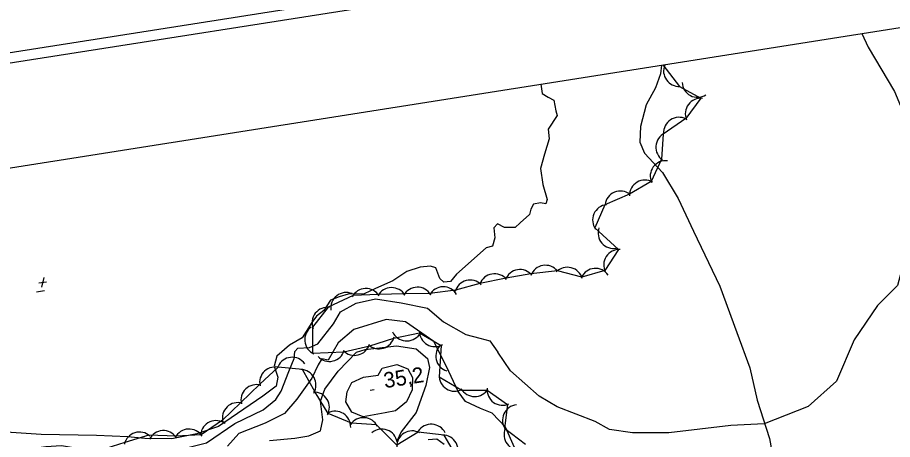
# Model space of a CAD drawing. Extents: x 646142 to 649934, y 5874075 to 5876351.
# Drawn here: x 647215 to 647384.4, y 5875891.3 to 5875973 of the extents above; entities that cross this region are included whole.
import ezdxf

# ---------------------------------------------------------------- set-up
doc = ezdxf.new("R2010")
doc.units = 0
for name, color, linetype in [('Niveau 1', 7, 'Continuous'), ('Niveau 2', 7, 'Continuous'), ('Niveau 22', 7, 'Continuous'), ('Niveau 3', 7, 'Continuous'), ('Niveau 4', 7, 'Continuous'), ('Niveau 44', 7, 'Continuous'), ('Niveau 60', 7, 'Continuous')]:
    doc.layers.add(name, color=color, linetype=linetype)

msp = doc.modelspace()

# ---------------------------------------------------------------- linework, layer by layer
at = {"layer": 'Niveau 1'}
msp.add_lwpolyline([(647311.2, 5875889.81), (647309.49, 5875893.7), (647306.91, 5875896.45), (647304.63, 5875897.32), (647301.71, 5875898.71), (647300.31, 5875900.65), (647298.04, 5875905.47), (647295.59, 5875910.32), (647290.14, 5875914.07), (647286.39, 5875914.56), (647280.1, 5875912.59), (647277.06, 5875910.02), (647275.13, 5875906.7), (647273.95, 5875906.93), (647273.2, 5875905.75), (647272.01, 5875903.19), (647269.11, 5875899.13), (647266.73, 5875896.34), (647262.98, 5875894.51), (647257.86, 5875892.49), (647255.67, 5875890.07)], dxfattribs=at)
at = {"layer": 'Niveau 2'}
for points in [[(647378.44, 5875969.85), (647379.63, 5875967.2), (647384.74, 5875958.65), (647387.38, 5875952.35), (647389.85, 5875944.82), (647390.07, 5875940.83), (647388.75, 5875934.2)], [(647388.75, 5875934.2), (647387.58, 5875929.55), (647385.33, 5875921.14), (647381.43, 5875917.26), (647376.93, 5875910.6), (647373.49, 5875902.65), (647368.06, 5875897.75), (647359.55, 5875894.34), (647353.1, 5875894.04), (647341.09, 5875892.6), (647334.02, 5875892.64), (647329.56, 5875893.29)], [(647266.06, 5875900.7), (647267.53, 5875904.51), (647268.56, 5875907), (647268.72, 5875908.35), (647269.29, 5875908.99), (647271.54, 5875909.1), (647273.15, 5875909.84), (647276.18, 5875913.69), (647277.57, 5875916.04), (647280.59, 5875917.73), (647284.28, 5875918.57), (647289.28, 5875917.74), (647294.36, 5875916.74), (647297.46, 5875914.09), (647301.82, 5875911.62), (647304.49, 5875910.96), (647306.46, 5875910.41), (647308, 5875908.24)], [(647263.83, 5875891.12), (647268.69, 5875891.61), (647271.41, 5875892.06), (647273.69, 5875892.99), (647274.11, 5875895.17), (647273.64, 5875898.77), (647274.51, 5875901.06), (647277.11, 5875904.56), (647280.61, 5875908.21), (647282.29, 5875908.73), (647288.4, 5875909.46), (647292.16, 5875908.85), (647294.36, 5875906.99), (647294.76, 5875905.24), (647294.06, 5875901.81), (647292.21, 5875896.59), (647289.29, 5875892.82), (647288.44, 5875891)], [(647329.56, 5875893.29), (647326.81, 5875894.81), (647319.46, 5875897.67), (647315.96, 5875899.75), (647310.44, 5875904.6), (647308, 5875908.24)], [(647286.17, 5875896.51), (647281.92, 5875895.73), (647279.76, 5875896.61), (647278.58, 5875898.63), (647278.85, 5875900.57), (647279.71, 5875902.39), (647281.98, 5875903.37), (647284.82, 5875903.77), (647285.61, 5875905.12), (647288.47, 5875905.87), (647290.58, 5875904.98), (647291.49, 5875903.34), (647291.38, 5875900.96), (647290.34, 5875898.6), (647288.15, 5875896.88), (647286.17, 5875896.51)], [(647214.46, 5875889.17), (647220.53, 5875889.96), (647223.53, 5875890.15), (647231.77, 5875888.83), (647236.33, 5875888.47), (647245.14, 5875889.07), (647251.64, 5875890.66), (647257.06, 5875894.46), (647262.59, 5875897.1), (647265, 5875899.09), (647266.06, 5875900.7)], [(647294.47, 5875891.32), (647296.18, 5875891.49), (647297.61, 5875890.42)]]:
    msp.add_lwpolyline(points, dxfattribs=at)
at = {"layer": 'Niveau 22'}
msp.add_lwpolyline([(647339.64, 5875963.74), (647339.49, 5875962.05), (647338.47, 5875959.38), (647336.71, 5875956.07), (647335.61, 5875951.88), (647335.45, 5875948.84), (647336.35, 5875946.72), (647339.85, 5875943), (647342.89, 5875937.96), (647345.83, 5875931.63), (647350.93, 5875920.98), (647354.24, 5875912.02), (647356.76, 5875905.19), (647358.18, 5875898.95), (647360.53, 5875891.52), (647361.78, 5875884.69), (647362.72, 5875877.36), (647363.99, 5875873.9), (647367.3, 5875864.85), (647371.22, 5875853.09), (647372.85, 5875844.69), (647375.07, 5875836.12), (647380.22, 5875826)], dxfattribs=at)
at = {"layer": 'Niveau 3'}
for p, q in [((647220.13, 5875922.67), (647219.67, 5875920.82)), ((647220.13, 5875922.67), (647219.67, 5875920.82)), ((647219.14, 5875921.61), (647220.68, 5875921.85)), ((647219.14, 5875921.61), (647220.68, 5875921.85)), ((647218.7, 5875919.92), (647220.28, 5875920.17)), ((647218.7, 5875919.92), (647220.28, 5875920.17)), ((647283.28, 5875900.86), (647284.07, 5875900.98))]:
    msp.add_line(p, q, dxfattribs=at)
at = {"layer": 'Niveau 4'}
msp.add_lwpolyline([(647316.33, 5875960.08), (647316.58, 5875958.24), (647317.7, 5875957.53), (647318.8, 5875956.95), (647319.23, 5875954.89), (647319.44, 5875953.98), (647317.72, 5875951.37), (647317.9, 5875949.52), (647317.04, 5875946.53), (647316.27, 5875943.77), (647316.69, 5875940.67), (647317.56, 5875937.74), (647317.29, 5875936.9), (647316.22, 5875937.14), (647314.86, 5875936.88), (647314.37, 5875935.9), (647314.13, 5875934.83), (647312.32, 5875933.25), (647311.36, 5875932.34), (647309.27, 5875932.37), (647307.93, 5875933.05), (647307.19, 5875932.27), (647307.39, 5875930.32), (647306.96, 5875928.76), (647305.72, 5875928.4), (647299.96, 5875923.29), (647298.82, 5875921.89), (647297.56, 5875921.77), (647296.79, 5875922.5), (647296.01, 5875924.52), (647294.93, 5875924.88), (647292.98, 5875924.68), (647290.4, 5875923.84), (647287.67, 5875922.05), (647284.34, 5875920.55), (647282.12, 5875919.51), (647279, 5875919.43), (647277.31, 5875918.91), (647275.63, 5875918.28), (647274.32, 5875916.29), (647272.92, 5875915.22), (647272, 5875913.96), (647270.09, 5875910.98), (647267.68, 5875909.57), (647265.22, 5875907.46), (647264.71, 5875905.55), (647265.39, 5875903.41), (647265.1, 5875901.63), (647262.5, 5875899.75), (647253.92, 5875893.88), (647249.77, 5875892.42), (647244.88, 5875891.46), (647239.65, 5875891.51), (647236.37, 5875891.88), (647230.31, 5875892.08), (647219.61, 5875892.28), (647212.83, 5875892.76)], dxfattribs=at)
at = {"layer": 'Niveau 44'}
for points in [[(647339.9, 5875963.78), (647343.15, 5875959.63), (647347.29, 5875957.34), (647344.39, 5875953.45), (647339.97, 5875950.42), (647339.62, 5875945.58), (647337.65, 5875941.26), (647333.46, 5875938.8), (647328.7, 5875936.7), (647326.72, 5875932.27), (647331.32, 5875928.06), (647328.67, 5875924), (647324.23, 5875922.74), (647319.53, 5875923.96), (647314.36, 5875923.35), (647309.57, 5875922.55), (647304.52, 5875921.49), (647299.82, 5875920.25), (647294.82, 5875919.6), (647289.97, 5875919.52), (647284.82, 5875919.4), (647279.97, 5875919.2), (647275.12, 5875916.91), (647272.14, 5875913.08), (647272.11, 5875908.05), (647278.16, 5875908.29), (647283.19, 5875909.47), (647287.83, 5875910.91), (647292.83, 5875912), (647297.02, 5875909.55), (647296.63, 5875903.47), (647301.04, 5875900.91), (647305.9, 5875900.87), (647309.85, 5875898.11), (647309.29, 5875893.56), (647313.32, 5875890.46)], [(647300.05, 5875887.98), (647297.61, 5875892.18), (647292.58, 5875892.76), (647288.42, 5875890.26), (647284.52, 5875894.17), (647279.68, 5875894.48), (647275.16, 5875896.37), (647272.64, 5875900.52), (647270.16, 5875904.85), (647265.46, 5875905.31), (647261.91, 5875902.01), (647258.2, 5875898.43), (647254.71, 5875895.05), (647250.56, 5875892.26), (647245.72, 5875891.97), (647240.42, 5875892.2)], [(647240.42, 5875892.2), (647235.79, 5875890.73), (647230.88, 5875889.18), (647226.26, 5875887.71), (647221.14, 5875888.24), (647216.34, 5875888.95), (647211.25, 5875889.73)]]:
    msp.add_lwpolyline(points, dxfattribs=at)
for centre, start, end in [((647343.05, 5875962.63), 158.0824, 273.0218), ((647346.64, 5875960.52), 182.351, 302.3289), ((647347.26, 5875954.34), 83.294, 203.2719), ((647343.05, 5875950.66), 63.4472, 183.4251), ((647341.55, 5875947.87), 115.8757, 235.8536), ((647340.47, 5875942.26), 83.3817, 203.3596), ((647336.45, 5875938.51), 60.4303, 180.4082), ((647331.7, 5875936.4), 52.5962, 172.5742), ((647329.32, 5875933.77), 95.9936, 215.9715), ((647330.38, 5875931.29), 160.9102, 280.8881), ((647331.47, 5875925.07), 86.8811, 206.859), ((647317.19, 5875922.04), 39.5217, 159.4997), ((647321.44, 5875921.65), 15.4721, 135.4501), ((647326.87, 5875921.44), 34.4337, 154.4116), ((647307.33, 5875920.39), 39.5217, 159.4997), ((647312.26, 5875921.21), 39.5217, 159.4997), ((647302.62, 5875919.17), 44.7986, 164.7766), ((647278.64, 5875916.77), 67.6972, 187.6751), ((647282.46, 5875917.54), 32.344, 152.3219), ((647287.42, 5875917.72), 30.892, 150.8699), ((647292.42, 5875917.8), 30.892, 150.8699), ((647297.42, 5875917.87), 30.892, 150.8699), ((647275.03, 5875913.91), 82.1223, 202.1002), ((647273.62, 5875910.64), 125.6786, 245.6566), ((647284.99, 5875911.87), 227.292, 347.2699), ((647290.36, 5875913.39), 204.4307, 324.4086), ((647295.82, 5875912.3), 179.6393, 299.6172), ((647280.26, 5875910.61), 223.4867, 343.4646), ((647298.99, 5875907.46), 132.6597, 252.6376), ((647275.39, 5875909.44), 223.4867, 343.4646), ((647268.19, 5875904.24), 35.7738, 155.7517), ((647264.89, 5875902.37), 72.8955, 192.8734), ((647269.79, 5875901.88), 328.8499, 88.8278), ((647299.63, 5875903.67), 177.7909, 297.7689), ((647261.28, 5875898.95), 74.0903, 194.0682), ((647303.48, 5875902.65), 209.5576, 329.5355), ((647308.9, 5875900.96), 174.4692, 294.4472), ((647272.39, 5875897.53), 331.2421, 91.22), ((647257.68, 5875895.48), 74.0903, 194.0682), ((647311.89, 5875895.06), 95.9938, 215.9717), ((647276.51, 5875893.8), 357.6803, 117.6583), ((647281.98, 5875892.56), 26.2907, 146.2686), ((647253.46, 5875891.99), 53.7726, 173.7505), ((647295.1, 5875891.29), 26.8766, 146.8545), ((647238.64, 5875889.78), 47.594, 167.572), ((647243.25, 5875890.06), 33.4361, 153.414), ((647248.25, 5875890.36), 33.4361, 153.414), ((647285.54, 5875890.35), 9.889, 129.867), ((647291.41, 5875890), 61.0844, 181.0624), ((647297.31, 5875889.19), 330.1996, 90.1775), ((647312.18, 5875892.27), 156.5905, 276.5685)]:
    msp.add_arc(centre, 3, start, end, dxfattribs=at)
at = {"layer": 'Niveau 60'}
for points in [[(646142.26, 5875797.64), (649662.59, 5876351.49), (649933.58, 5874629.01), (646413.32, 5874074.83), (646142.26, 5875797.64)], [(646144.55, 5875795.97), (649660.92, 5876349.21), (649931.28, 5874630.65), (646414.98, 5874077.12), (646144.55, 5875795.97)]]:
    msp.add_lwpolyline(points, dxfattribs=at)
msp.add_lwpolyline([(646167.42, 5875779.32), (649130.97, 5876245.57), (649395.18, 5874566.24), (646431.63, 5874099.99)], close=True, dxfattribs=at)
msp.add_lwpolyline([(646167.42, 5875779.32), (649130.97, 5876245.57), (649395.18, 5874566.24), (646431.63, 5874099.99)], close=True, dxfattribs=at)

# ---------------------------------------------------------------- texts
at = {"layer": 'Niveau 3'}
msp.add_text('35,2 ', height=3, rotation=8.9405, dxfattribs=at).set_placement((647286.13, 5875901.26))

doc.saveas('drawing.dxf')
